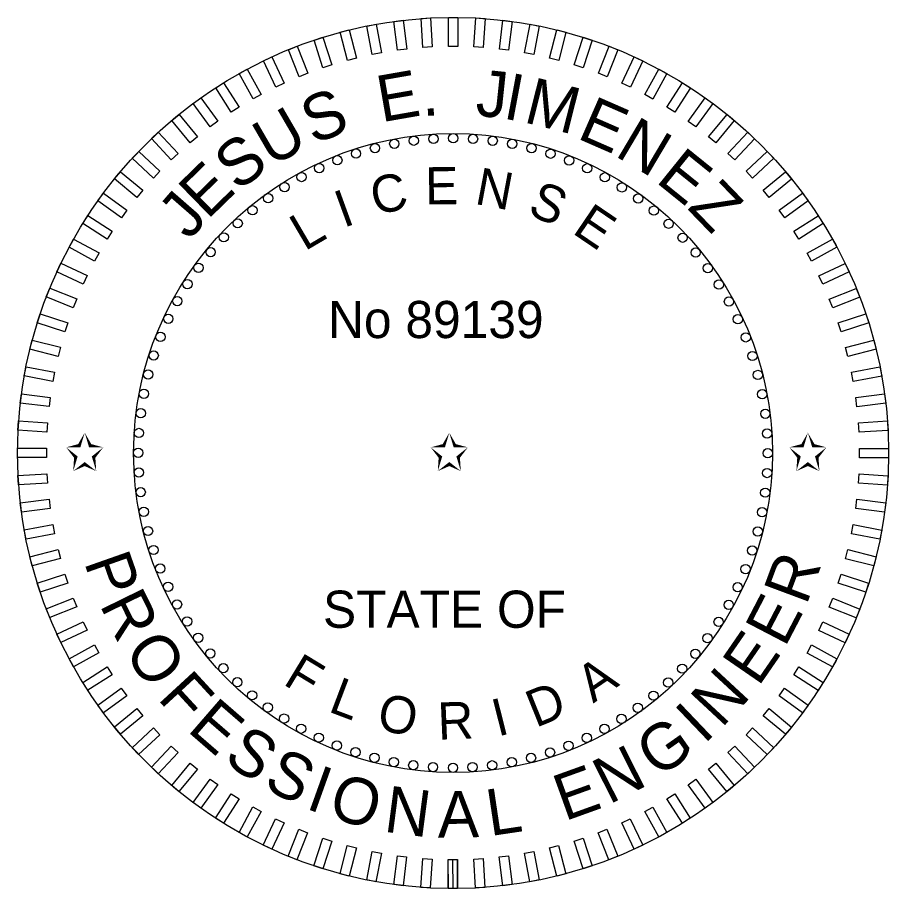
# Model space of a CAD drawing. Extents: x -816.9 to -790.1, y -2199.5 to -2188.9.
# Drawn here: x -816.89 to -815.015, y -2191.63 to -2189.755 of the extents above; entities that cross this region are included whole.
import ezdxf

# ---------------------------------------------------------------- set-up
doc = ezdxf.new("R2010")
doc.units = 0
doc.layers.add('Logo_dp', color=7, linetype='Continuous')
doc.layers.add('NonPlottingEle_dp', color=7, linetype='Continuous')

msp = doc.modelspace()

# ---------------------------------------------------------------- linework, layer by layer
at = {"layer": 'Logo_dp'}
for p, q in [((-815.9624, -2191.6301), (-815.9626, -2191.5676)), ((-815.9524, -2191.6301), (-815.9526, -2191.5676)), ((-815.9424, -2191.6301), (-815.9426, -2191.5676))]:
    msp.add_line(p, q, dxfattribs=at)
for points in [[(-816.1064, -2189.8311), (-816.1262, -2189.8349), (-816.1379, -2189.7736), (-816.1181, -2189.7698)], [(-816.052, -2189.8232), (-816.072, -2189.8257), (-816.0798, -2189.7638), (-816.0598, -2189.7612)], [(-815.9972, -2189.8186), (-816.0174, -2189.8199), (-816.0213, -2189.7576), (-816.0011, -2189.7563)], [(-815.9422, -2189.8176), (-815.9624, -2189.8176), (-815.9624, -2189.7551), (-815.9422, -2189.7551)], [(-815.8873, -2189.8199), (-815.9075, -2189.8186), (-815.9035, -2189.7563), (-815.8834, -2189.7576)], [(-815.8327, -2189.8257), (-815.8527, -2189.8232), (-815.8449, -2189.7612), (-815.8248, -2189.7638)], [(-815.7785, -2189.835), (-815.7983, -2189.8312), (-815.7866, -2189.7698), (-815.7668, -2189.7736)], [(-816.1602, -2189.8425), (-816.1797, -2189.8475), (-816.1953, -2189.787), (-816.1757, -2189.782)], [(-815.725, -2189.8476), (-815.7445, -2189.8426), (-815.729, -2189.7821), (-815.7094, -2189.7871)], [(-816.2131, -2189.8572), (-816.2323, -2189.8635), (-816.2516, -2189.8041), (-816.2324, -2189.7978)], [(-815.6723, -2189.8635), (-815.6915, -2189.8573), (-815.6722, -2189.7979), (-815.653, -2189.8041)], [(-816.2651, -2189.8752), (-816.2838, -2189.8827), (-816.3068, -2189.8246), (-816.2881, -2189.8172)], [(-815.6208, -2189.8827), (-815.6396, -2189.8753), (-815.6166, -2189.8173), (-815.5979, -2189.8247)], [(-816.3158, -2189.8965), (-816.334, -2189.9051), (-816.3606, -2189.8486), (-816.3424, -2189.84)], [(-815.5706, -2189.9052), (-815.5889, -2189.8966), (-815.5623, -2189.8401), (-815.5441, -2189.8487)], [(-816.3651, -2189.9209), (-816.3827, -2189.9306), (-816.4128, -2189.8759), (-816.3951, -2189.8662)], [(-815.522, -2189.9307), (-815.5396, -2189.921), (-815.5096, -2189.8663), (-815.4919, -2189.876)], [(-816.4127, -2189.9483), (-816.4297, -2189.9591), (-816.4632, -2189.9064), (-816.4462, -2189.8956)], [(-815.475, -2189.9592), (-815.492, -2189.9484), (-815.4586, -2189.8957), (-815.4415, -2189.9065)], [(-816.4585, -2189.9787), (-816.4749, -2189.9905), (-816.5116, -2189.94), (-816.4952, -2189.9282)], [(-815.4299, -2189.9907), (-815.4462, -2189.9788), (-815.4095, -2189.9283), (-815.3932, -2189.9401)], [(-816.5023, -2190.0119), (-816.5179, -2190.0247), (-816.5577, -2189.9766), (-816.5421, -2189.9638)], [(-815.3868, -2190.0249), (-815.4024, -2190.012), (-815.3626, -2189.9639), (-815.347, -2189.9767)], [(-816.544, -2190.0477), (-816.5587, -2190.0616), (-816.6015, -2190.016), (-816.5867, -2190.0022)], [(-815.346, -2190.0617), (-815.3607, -2190.0479), (-815.318, -2190.0023), (-815.3033, -2190.0162)], [(-816.5833, -2190.0862), (-816.5971, -2190.1009), (-816.6427, -2190.0581), (-816.6288, -2190.0434)], [(-815.3076, -2190.101), (-815.3214, -2190.0863), (-815.2759, -2190.0435), (-815.2621, -2190.0583)], [(-816.6202, -2190.127), (-816.633, -2190.1425), (-816.6811, -2190.1027), (-816.6683, -2190.0872)], [(-815.2717, -2190.1427), (-815.2846, -2190.1271), (-815.2365, -2190.0873), (-815.2236, -2190.1029)], [(-816.6544, -2190.17), (-816.6662, -2190.1863), (-816.7167, -2190.1496), (-816.7049, -2190.1333)], [(-815.2385, -2190.1865), (-815.2504, -2190.1702), (-815.1999, -2190.1335), (-815.188, -2190.1498)], [(-816.6858, -2190.2151), (-816.6966, -2190.2322), (-816.7493, -2190.1987), (-816.7385, -2190.1817)], [(-815.2082, -2190.2323), (-815.219, -2190.2153), (-815.1663, -2190.1818), (-815.1554, -2190.1989)], [(-816.7143, -2190.2621), (-816.724, -2190.2798), (-816.7788, -2190.2497), (-816.769, -2190.232)], [(-815.1807, -2190.28), (-815.1905, -2190.2623), (-815.1357, -2190.2322), (-815.126, -2190.2499)], [(-816.7398, -2190.3108), (-816.7484, -2190.3291), (-816.8049, -2190.3025), (-816.7963, -2190.2842)], [(-815.1563, -2190.3292), (-815.1649, -2190.311), (-815.1084, -2190.2844), (-815.0998, -2190.3026)], [(-816.7623, -2190.361), (-816.7697, -2190.3798), (-816.8278, -2190.3568), (-816.8203, -2190.338)], [(-815.1351, -2190.3799), (-815.1425, -2190.3612), (-815.0845, -2190.3382), (-815.077, -2190.3569)], [(-816.7815, -2190.4125), (-816.7877, -2190.4317), (-816.8471, -2190.4124), (-816.8409, -2190.3932)], [(-815.1171, -2190.4319), (-815.1233, -2190.4127), (-815.0639, -2190.3934), (-815.0577, -2190.4126)], [(-816.7974, -2190.4651), (-816.8025, -2190.4847), (-816.8629, -2190.4691), (-816.8579, -2190.4496)], [(-815.1024, -2190.4848), (-815.1074, -2190.4653), (-815.0469, -2190.4498), (-815.0419, -2190.4693)], [(-816.8101, -2190.5186), (-816.8138, -2190.5384), (-816.8752, -2190.5267), (-816.8714, -2190.5069)], [(-815.091, -2190.5386), (-815.0948, -2190.5188), (-815.0334, -2190.5071), (-815.0297, -2190.5269)], [(-816.8193, -2190.5728), (-816.8218, -2190.5928), (-816.8838, -2190.585), (-816.8812, -2190.565)], [(-815.083, -2190.593), (-815.0856, -2190.573), (-815.0236, -2190.5652), (-815.0211, -2190.5852)], [(-816.8251, -2190.6275), (-816.8264, -2190.6476), (-816.8887, -2190.6437), (-816.8874, -2190.6236)], [(-815.0785, -2190.6478), (-815.0798, -2190.6277), (-815.0174, -2190.6237), (-815.0162, -2190.6439)], [(-816.8275, -2190.6824), (-816.8275, -2190.7026), (-816.8899, -2190.7026), (-816.8899, -2190.6824)], [(-815.0774, -2190.7028), (-815.0774, -2190.6826), (-815.015, -2190.6826), (-815.015, -2190.7028)], [(-816.8264, -2190.7374), (-816.8251, -2190.7575), (-816.8874, -2190.7614), (-816.8887, -2190.7413)], [(-815.0798, -2190.7577), (-815.0785, -2190.7375), (-815.0162, -2190.7415), (-815.0175, -2190.7616)], [(-816.8218, -2190.7921), (-816.8193, -2190.8122), (-816.8813, -2190.82), (-816.8838, -2190.8)], [(-815.0856, -2190.8124), (-815.083, -2190.7923), (-815.0211, -2190.8002), (-815.0236, -2190.8202)], [(-816.8139, -2190.8465), (-816.8101, -2190.8664), (-816.8714, -2190.8781), (-816.8752, -2190.8582)], [(-815.0948, -2190.8666), (-815.091, -2190.8467), (-815.0297, -2190.8584), (-815.0335, -2190.8783)], [(-816.8025, -2190.9003), (-816.7975, -2190.9199), (-816.858, -2190.9354), (-816.863, -2190.9159)], [(-815.1074, -2190.9201), (-815.1024, -2190.9005), (-815.0419, -2190.916), (-815.0469, -2190.9356)], [(-816.7878, -2190.9533), (-816.7815, -2190.9725), (-816.8409, -2190.9918), (-816.8472, -2190.9726)], [(-815.1234, -2190.9727), (-815.1171, -2190.9535), (-815.0578, -2190.9728), (-815.064, -2190.992)], [(-816.7698, -2191.0052), (-816.7623, -2191.024), (-816.8204, -2191.047), (-816.8278, -2191.0282)], [(-815.1426, -2191.0242), (-815.1352, -2191.0054), (-815.0771, -2191.0284), (-815.0845, -2191.0472)], [(-816.7485, -2191.0559), (-816.7399, -2191.0742), (-816.7964, -2191.1008), (-816.805, -2191.0825)], [(-815.165, -2191.0744), (-815.1564, -2191.0561), (-815.0999, -2191.0827), (-815.1085, -2191.101)], [(-816.7241, -2191.1052), (-816.7144, -2191.1229), (-816.7691, -2191.153), (-816.7788, -2191.1353)], [(-815.1905, -2191.1231), (-815.1808, -2191.1054), (-815.1261, -2191.1354), (-815.1358, -2191.1531)], [(-816.6967, -2191.1528), (-816.6859, -2191.1699), (-816.7386, -2191.2033), (-816.7494, -2191.1863)], [(-815.2191, -2191.17), (-815.2083, -2191.153), (-815.1555, -2191.1865), (-815.1664, -2191.2035)], [(-816.6663, -2191.1987), (-816.6545, -2191.215), (-816.705, -2191.2517), (-816.7168, -2191.2354)], [(-815.2505, -2191.2152), (-815.2386, -2191.1988), (-815.1881, -2191.2355), (-815.2, -2191.2519)], [(-816.6331, -2191.2425), (-816.6203, -2191.2581), (-816.6684, -2191.2979), (-816.6813, -2191.2823)], [(-815.2847, -2191.2582), (-815.2718, -2191.2426), (-815.2237, -2191.2824), (-815.2366, -2191.298)], [(-816.5973, -2191.2842), (-816.5835, -2191.2989), (-816.629, -2191.3416), (-816.6428, -2191.3269)], [(-815.3215, -2191.299), (-815.3077, -2191.2843), (-815.2622, -2191.327), (-815.276, -2191.3417)], [(-816.5589, -2191.3235), (-816.5441, -2191.3373), (-816.5869, -2191.3828), (-816.6016, -2191.369)], [(-815.3609, -2191.3374), (-815.3461, -2191.3236), (-815.3034, -2191.3691), (-815.3181, -2191.3829)], [(-816.518, -2191.3603), (-816.5025, -2191.3732), (-816.5423, -2191.4213), (-816.5578, -2191.4084)], [(-815.4025, -2191.3733), (-815.387, -2191.3604), (-815.3472, -2191.4085), (-815.3627, -2191.4214)], [(-816.475, -2191.3945), (-816.4587, -2191.4064), (-816.4954, -2191.4569), (-816.5117, -2191.445)], [(-815.4463, -2191.4065), (-815.43, -2191.3946), (-815.3933, -2191.4451), (-815.4096, -2191.457)], [(-816.4299, -2191.4259), (-816.4129, -2191.4368), (-816.4463, -2191.4895), (-816.4634, -2191.4787)], [(-815.4922, -2191.4369), (-815.4751, -2191.426), (-815.4417, -2191.4788), (-815.4587, -2191.4896)], [(-816.3829, -2191.4545), (-816.3652, -2191.4642), (-816.3953, -2191.5189), (-816.413, -2191.5092)], [(-815.5398, -2191.4643), (-815.5221, -2191.4546), (-815.492, -2191.5093), (-815.5097, -2191.519)], [(-816.3342, -2191.48), (-816.316, -2191.4886), (-816.3425, -2191.5451), (-816.3608, -2191.5365)], [(-815.5891, -2191.4887), (-815.5708, -2191.4801), (-815.5442, -2191.5366), (-815.5625, -2191.5452)], [(-816.284, -2191.5024), (-816.2653, -2191.5098), (-816.2882, -2191.5679), (-816.307, -2191.5605)], [(-815.6398, -2191.5099), (-815.621, -2191.5025), (-815.598, -2191.5605), (-815.6168, -2191.568)], [(-816.2325, -2191.5216), (-816.2133, -2191.5279), (-816.2326, -2191.5873), (-816.2518, -2191.581)], [(-815.6917, -2191.5279), (-815.6725, -2191.5217), (-815.6532, -2191.5811), (-815.6724, -2191.5873)], [(-816.1799, -2191.5376), (-816.1604, -2191.5426), (-816.1759, -2191.6031), (-816.1954, -2191.5981)], [(-816.1264, -2191.5502), (-816.1066, -2191.554), (-816.1183, -2191.6153), (-816.1381, -2191.6115)], [(-815.7985, -2191.554), (-815.7786, -2191.5502), (-815.7669, -2191.6116), (-815.7868, -2191.6154)], [(-815.7447, -2191.5427), (-815.7251, -2191.5376), (-815.7096, -2191.5981), (-815.7292, -2191.6031)], [(-816.0722, -2191.5594), (-816.0522, -2191.562), (-816.06, -2191.6239), (-816.08, -2191.6214)], [(-816.0175, -2191.5652), (-815.9974, -2191.5665), (-816.0013, -2191.6288), (-816.0215, -2191.6276)], [(-815.9626, -2191.5676), (-815.9424, -2191.5676), (-815.9424, -2191.6301), (-815.9626, -2191.6301)], [(-815.9077, -2191.5665), (-815.8875, -2191.5653), (-815.8836, -2191.6276), (-815.9037, -2191.6288)], [(-815.8529, -2191.562), (-815.8328, -2191.5595), (-815.825, -2191.6214), (-815.845, -2191.6239)]]:
    msp.add_lwpolyline(points, close=True, dxfattribs=at)
for centre in [(-816.0368, -2190.0204), (-815.9944, -2190.0164), (-815.9519, -2190.0151), (-815.9093, -2190.0165), (-815.867, -2190.0205), (-816.1204, -2190.0363), (-816.0788, -2190.027), (-815.8249, -2190.0272), (-815.7834, -2190.0365), (-816.2013, -2190.0625), (-816.1612, -2190.0481), (-815.7425, -2190.0484), (-815.7025, -2190.0629), (-816.2404, -2190.0793), (-815.6635, -2190.0798), (-816.2783, -2190.0986), (-815.6256, -2190.0992), (-816.315, -2190.1203), (-815.5889, -2190.1209), (-816.3502, -2190.1442), (-815.5538, -2190.1448), (-816.3838, -2190.1702), (-815.5202, -2190.1709), (-816.4158, -2190.1983), (-815.4883, -2190.1991), (-816.4459, -2190.2284), (-815.4582, -2190.2292), (-816.4741, -2190.2603), (-815.4301, -2190.2612), (-816.5002, -2190.2939), (-815.404, -2190.2948), (-816.5241, -2190.3291), (-815.3801, -2190.3301), (-816.5458, -2190.3657), (-815.3585, -2190.3667), (-816.5652, -2190.4036), (-815.3392, -2190.4046), (-816.5821, -2190.4427), (-815.3223, -2190.4437), (-816.5966, -2190.4827), (-815.3079, -2190.4838), (-816.6085, -2190.5236), (-815.2961, -2190.5246), (-816.6178, -2190.5651), (-815.2869, -2190.5662), (-816.6245, -2190.6071), (-815.2802, -2190.6082), (-816.6285, -2190.6495), (-815.2763, -2190.6506), (-816.6299, -2190.692), (-815.275, -2190.6931), (-816.6286, -2190.7346), (-815.2763, -2190.7357), (-816.6246, -2190.7769), (-815.2804, -2190.778), (-816.618, -2190.819), (-815.2871, -2190.8201), (-816.6088, -2190.8605), (-815.2964, -2190.8616), (-816.5969, -2190.9014), (-815.3083, -2190.9025), (-816.5825, -2190.9414), (-815.3227, -2190.9425), (-816.5657, -2190.9805), (-815.3397, -2190.9815), (-816.5464, -2191.0185), (-815.359, -2191.0194), (-816.5247, -2191.0551), (-815.3807, -2191.0561), (-816.5008, -2191.0903), (-815.4047, -2191.0912), (-816.4748, -2191.124), (-815.4308, -2191.1248), (-816.4467, -2191.1559), (-815.459, -2191.1568), (-816.4166, -2191.186), (-815.4891, -2191.1868), (-816.3847, -2191.2142), (-815.521, -2191.2149), (-816.3511, -2191.2403), (-815.5547, -2191.241), (-816.3159, -2191.2643), (-815.5899, -2191.2649), (-816.2793, -2191.286), (-815.6266, -2191.2865), (-816.2414, -2191.3053), (-815.6645, -2191.3058), (-816.2023, -2191.3223), (-816.1623, -2191.3367), (-815.7436, -2191.3371), (-815.7036, -2191.3227), (-816.1215, -2191.3486), (-815.7845, -2191.3489), (-816.0799, -2191.3579), (-816.0379, -2191.3646), (-815.9955, -2191.3687), (-815.9524, -2191.3701), (-815.9105, -2191.3687), (-815.8681, -2191.3648), (-815.826, -2191.3582)]:
    msp.add_circle(centre, 0.01, dxfattribs=at)
at = {"layer": 'NonPlottingEle_dp'}
for radius in [0.9375, 0.6875]:
    msp.add_circle((-815.9524, -2190.6926), radius, dxfattribs=at)

# ---------------------------------------------------------------- texts
at = {"layer": 'Logo_dp'}
for s, height, rotation, p in [('E', 0.1, 9.905, (-816.1066, -2189.981)), ('J', 0.1, 354.0087, (-815.9058, -2189.966)), ('I', 0.1, 349.3642, (-815.8471, -2189.9721)), ('M', 0.1, 345.831, (-815.8029, -2189.98)), ('S', 0.1, 22.0568, (-816.253, -2190.0294)), ('E', 0.1, 336.385, (-815.688, -2190.0142)), ('U', 0.1, 30.1439, (-816.3433, -2190.0783)), ('.', 0.1, 2.8628, (-816.0182, -2189.9675)), ('N', 0.1, 329.3427, (-815.6068, -2190.0517)), ('S', 0.1, 37.2163, (-816.4159, -2190.1311)), ('E', 0.1, 321.0926, (-815.5185, -2190.1079)), ('E', 0.1, 44.2586, (-816.4813, -2190.1921)), ('C', 0.08, 12.2025, (-816.1202, -2190.181)), ('E', 0.08, 0.4186, (-816.0122, -2190.1575)), ('N', 0.08, 349.2914, (-815.9078, -2190.156)), ('Z', 0.1, 314.0503, (-815.4501, -2190.1656)), ('J', 0.1, 48.9031, (-816.5201, -2190.2366)), ('I', 0.08, 20.0117, (-816.1881, -2190.2085)), ('S', 0.08, 337.0221, (-815.7948, -2190.1778)), ('E', 0.08, 325.8663, (-815.6981, -2190.218)), ('L', 0.08, 30.4021, (-816.2716, -2190.259)), ('P', 0.1, 289.4055, (-816.7471, -2190.9272)), ('R', 0.1, 69.5134, (-815.1922, -2191.0223)), ('R', 0.1, 296.1458, (-816.7141, -2191.0188)), ('E', 0.1, 62.4712, (-815.2384, -2191.113)), ('O', 0.1, 303.9671, (-816.6626, -2191.1194)), ('E', 0.1, 55.4289, (-815.2953, -2191.1974)), ('F', 0.08, 328.7241, (-816.3205, -2191.1892)), ('A', 0.08, 34.4992, (-815.6506, -2191.232)), ('N', 0.1, 47.1788, (-815.3746, -2191.2864)), ('F', 0.1, 312.628, (-816.5903, -2191.2215)), ('L', 0.08, 339.2916, (-816.2232, -2191.2482)), ('D', 0.08, 22.0128, (-815.7744, -2191.2845)), ('O', 0.08, 349.6821, (-816.1185, -2191.288)), ('E', 0.1, 319.0783, (-816.5268, -2191.2898)), ('R', 0.08, 2.3398, (-815.984, -2191.3099)), ('I', 0.08, 14.2037, (-815.8564, -2191.3032)), ('I', 0.1, 43.6456, (-815.4123, -2191.3209)), ('G', 0.1, 35.1115, (-815.5115, -2191.3941)), ('S', 0.1, 326.1206, (-816.4492, -2191.3557)), ('N', 0.1, 26.8614, (-815.6167, -2191.4501)), ('S', 0.1, 333.193, (-816.3638, -2191.4119)), ('E', 0.1, 19.8191, (-815.7121, -2191.4856)), ('I', 0.1, 340.2654, (-816.2721, -2191.457)), ('O', 0.1, 343.7986, (-816.2244, -2191.4753)), ('N', 0.1, 352.4595, (-816.1034, -2191.5073)), ('A', 0.1, 0.7097, (-815.985, -2191.5205)), ('L', 0.1, 8.4767, (-815.8728, -2191.5173))]:
    msp.add_text(s, height=height, rotation=rotation, dxfattribs=at).set_placement(p)
for s, p in [('No 89139', (-816.2214, -2190.4453)), ('✩', (-816.7874, -2190.7305)), ('✩', (-816.0027, -2190.7305)), ('✩', (-815.2309, -2190.7305)), ('STATE OF', (-816.2322, -2191.0688))]:
    msp.add_text(s, height=0.08, dxfattribs=at).set_placement(p)

doc.saveas('drawing.dxf')
